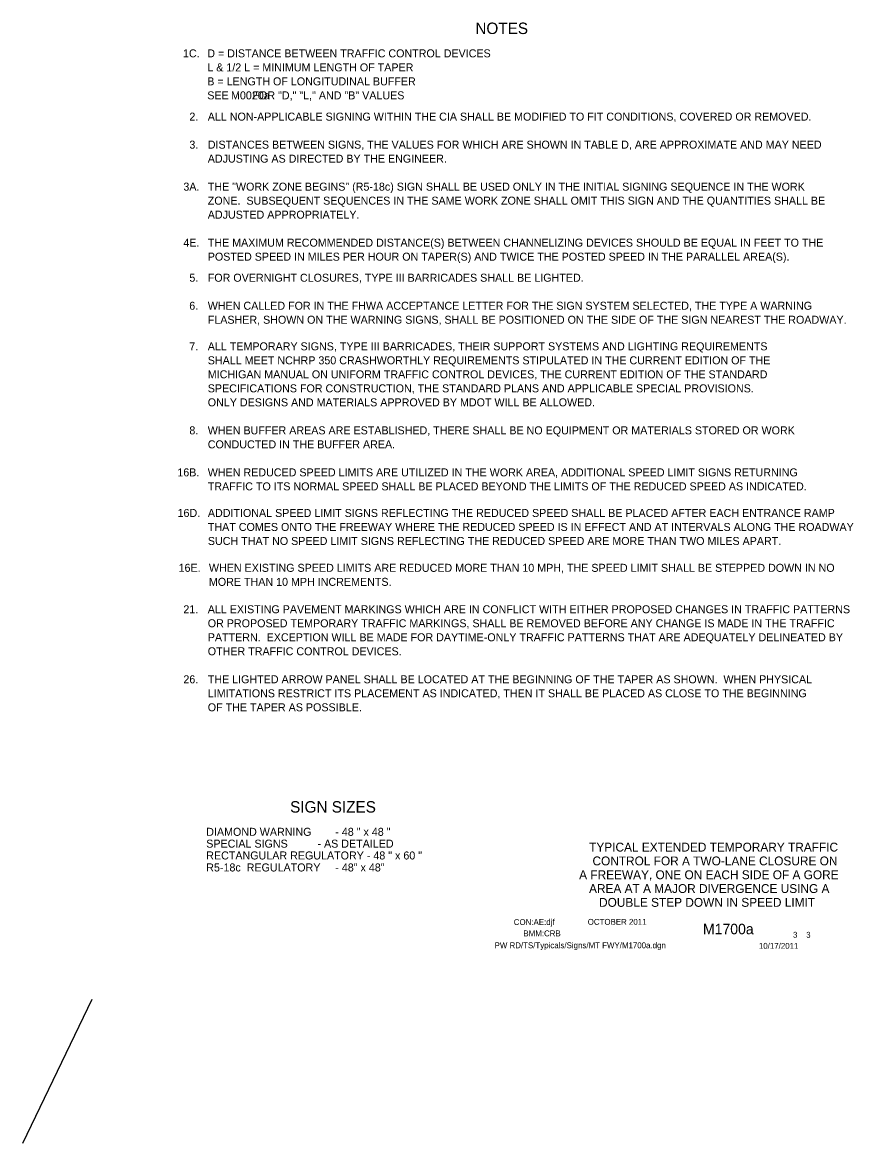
# Model space of a CAD drawing. Extents: x 16486 to 19505, y 5576 to 6998.
# Drawn here: x 18633 to 19505, y 5729 to 6905 of the extents above; entities that cross this region are included whole.
import ezdxf

# ---------------------------------------------------------------- set-up
doc = ezdxf.new("R2010")
doc.units = 0
for name, color, linetype in [('BORDER', 7, 'Continuous'), ('BORDER_SIGNAL_WO', 7, 'Continuous'), ('TYPICAL_TEXT_DIMEN_PR', 7, 'Continuous')]:
    doc.layers.add(name, color=color, linetype=linetype)

msp = doc.modelspace()

# ---------------------------------------------------------------- linework, layer by layer
at = {"layer": 'TYPICAL_TEXT_DIMEN_PR'}
msp.add_line((18705.8, 5880), (18633.1, 5728.7), dxfattribs=at)

# ---------------------------------------------------------------- texts
at = {"layer": 'BORDER'}
for s, p in [('TYPICAL EXTENDED TEMPORARY TRAFFIC', (19227.8, 6035.2)), ('CONTROL FOR A TWO-LANE CLOSURE ON', (19231.3, 6020.7)), ('A FREEWAY, ONE ON EACH SIDE OF A GORE', (19217.3, 6006.2)), ('AREA AT A MAJOR DIVERGENCE USING A', (19227.7, 5991.7)), ('DOUBLE STEP DOWN IN SPEED LIMIT', (19238.2, 5977.2))]:
    msp.add_text(s, height=9.3, dxfattribs=at).set_placement(p)
at = {"layer": 'BORDER_SIGNAL_WO'}
for s, height, p in [('CON:AE:djf  ', 6.2, (19148.7, 5958.1)), ('    OCTOBER 2011', 6.2, (19217.1, 5958.3)), ('    M1700a   ', 11, (19330.9, 5948.4)), ('BMM:CRB', 6.2, (19158.8, 5946.2)), (' 3    3 ', 6.2, (19439.4, 5944.7)), ('PW RD/TS/Typicals/Signs/MT FWY/M1700a.dgn      ', 6.2, (19128.6, 5933.7)), ('10/17/2011', 6.2, (19405.9, 5933.1))]:
    msp.add_text(s, height=height, dxfattribs=at).set_placement(p)
at = {"layer": 'TYPICAL_TEXT_DIMEN_PR'}
for s, height, p in [('NOTES', 12, (19108.4, 6893.3)), ('1C.', 8.4, (18801.6, 6868.8)), ('D = DISTANCE BETWEEN TRAFFIC CONTROL DEVICES', 8.4, (18827.1, 6868.8)), ('L & 1/2 L = MINIMUM LENGTH OF TAPER', 8.4, (18827.1, 6854.1)), ('B = LENGTH OF LONGITUDINAL BUFFER', 8.4, (18827.1, 6839.4)), ('SEE        FOR "D," "L," AND "B" VALUES', 8.4, (18827.1, 6824.7)), ('M0020a', 8.4, (18852, 6824.7)), ('2.', 8.4, (18808.3, 6802.4)), ('ALL NON-APPLICABLE SIGNING WITHIN THE CIA SHALL BE MODIFIED TO FIT CONDITIONS, COVERED OR REMOVED.', 8.4, (18827.6, 6802.4)), ('3.', 8.4, (18808.3, 6773)), ('DISTANCES BETWEEN SIGNS, THE VALUES FOR WHICH ARE SHOWN IN TABLE D, ARE APPROXIMATE AND MAY NEED', 8.4, (18827.6, 6773)), ('ADJUSTING AS DIRECTED BY THE ENGINEER.', 8.4, (18827.6, 6758.3)), ('3A.', 8.4, (18802, 6728.9)), ('THE "WORK ZONE BEGINS" (R5-18c) SIGN SHALL BE USED ONLY IN THE INITIAL SIGNING SEQUENCE IN THE WORK', 8.4, (18827.6, 6728.9)), ('ZONE.  SUBSEQUENT SEQUENCES IN THE SAME WORK ZONE SHALL OMIT THIS SIGN AND THE QUANTITIES SHALL BE', 8.4, (18827.6, 6714.2)), ('ADJUSTED APPROPRIATELY.', 8.4, (18827.6, 6699.5)), ('4E.', 8.4, (18802, 6670.1)), ('THE MAXIMUM RECOMMENDED DISTANCE(S) BETWEEN CHANNELIZING DEVICES SHOULD BE EQUAL IN FEET TO THE', 8.4, (18827.6, 6670.1)), ('POSTED SPEED IN MILES PER HOUR ON TAPER(S) AND TWICE THE POSTED SPEED IN THE PARALLEL AREA(S).', 8.4, (18827.6, 6655.4)), ('5.', 8.4, (18808.3, 6633.3)), ('FOR OVERNIGHT CLOSURES, TYPE III BARRICADES SHALL BE LIGHTED.', 8.4, (18827.6, 6633.3)), ('6.', 8.4, (18808.2, 6603.9)), ('WHEN CALLED FOR IN THE FHWA ACCEPTANCE LETTER FOR THE SIGN SYSTEM SELECTED, THE TYPE A WARNING ', 8.4, (18827.6, 6603.9)), ('FLASHER, SHOWN ON THE WARNING SIGNS, SHALL BE POSITIONED ON THE SIDE OF THE SIGN NEAREST THE ROADWAY.', 8.4, (18827.6, 6589.2)), ('7.', 8.4, (18808.2, 6561.3)), ('ALL TEMPORARY SIGNS, TYPE III BARRICADES, THEIR SUPPORT SYSTEMS AND LIGHTING REQUIREMENTS', 8.4, (18827.6, 6561.3)), ('SHALL MEET NCHRP 350 CRASHWORTHLY REQUIREMENTS STIPULATED IN THE CURRENT EDITION OF THE', 8.4, (18827.6, 6546.6)), ('MICHIGAN MANUAL ON UNIFORM TRAFFIC CONTROL DEVICES, THE CURRENT EDITION OF THE STANDARD', 8.4, (18827.6, 6531.9)), ('SPECIFICATIONS FOR CONSTRUCTION, THE STANDARD PLANS AND APPLICABLE SPECIAL PROVISIONS.', 8.4, (18827.6, 6517.2)), ('ONLY DESIGNS AND MATERIALS APPROVED BY MDOT WILL BE ALLOWED.', 8.4, (18827.6, 6502.5)), ('8.', 8.4, (18808.3, 6473.1)), ('WHEN BUFFER AREAS ARE ESTABLISHED, THERE SHALL BE NO EQUIPMENT OR MATERIALS STORED OR WORK     ', 8.4, (18827.6, 6473.1)), ('CONDUCTED IN THE BUFFER AREA.', 8.4, (18827.6, 6458.4)), ('16B.', 8.4, (18795.7, 6429)), ('WHEN REDUCED SPEED LIMITS ARE UTILIZED IN THE WORK AREA, ADDITIONAL SPEED LIMIT SIGNS RETURNING', 8.4, (18827.6, 6429)), ('TRAFFIC TO ITS NORMAL SPEED SHALL BE PLACED BEYOND THE LIMITS OF THE REDUCED SPEED AS INDICATED.', 8.4, (18827.6, 6414.3)), ('16D.', 8.4, (18795.9, 6386.4)), ('ADDITIONAL SPEED LIMIT SIGNS REFLECTING THE REDUCED SPEED SHALL BE PLACED AFTER EACH ENTRANCE RAMP', 8.4, (18827.7, 6386.4)), ('THAT COMES ONTO THE FREEWAY WHERE THE REDUCED SPEED IS IN EFFECT AND AT INTERVALS ALONG THE ROADWAY', 8.4, (18827.7, 6371.7)), ('SUCH THAT NO SPEED LIMIT SIGNS REFLECTING THE REDUCED SPEED ARE MORE THAN TWO MILES APART.', 8.4, (18827.7, 6357)), ('16E.', 8.4, (18797, 6328.8)), ('WHEN EXISTING SPEED LIMITS ARE REDUCED MORE THAN 10 MPH, THE SPEED LIMIT SHALL BE STEPPED DOWN IN NO', 8.4, (18828.8, 6328.8)), ('MORE THAN 10 MPH INCREMENTS.', 8.4, (18828.8, 6314.1)), ('21.', 8.4, (18802, 6285.3)), ('ALL EXISTING PAVEMENT MARKINGS WHICH ARE IN CONFLICT WITH EITHER PROPOSED CHANGES IN TRAFFIC PATTERNS', 8.4, (18827.6, 6285.3)), ('OR PROPOSED TEMPORARY TRAFFIC MARKINGS, SHALL BE REMOVED BEFORE ANY CHANGE IS MADE IN THE TRAFFIC', 8.4, (18827.6, 6270.6)), ('PATTERN.  EXCEPTION WILL BE MADE FOR DAYTIME-ONLY TRAFFIC PATTERNS THAT ARE ADEQUATELY DELINEATED BY', 8.4, (18827.6, 6255.9)), ('OTHER TRAFFIC CONTROL DEVICES.', 8.4, (18827.6, 6241.2)), ('26.', 8.4, (18802, 6211.8)), ('THE LIGHTED ARROW PANEL SHALL BE LOCATED AT THE BEGINNING OF THE TAPER AS SHOWN.  WHEN PHYSICAL', 8.4, (18827.6, 6211.8)), ('LIMITATIONS RESTRICT ITS PLACEMENT AS INDICATED, THEN IT SHALL BE PLACED AS CLOSE TO THE BEGINNING', 8.4, (18827.6, 6197.1)), ('OF THE TAPER AS POSSIBLE.', 8.4, (18827.6, 6182.4)), ('SIGN SIZES', 12, (18914, 6076.1)), ('DIAMOND WARNING        - 48 " x 48 "', 8.4, (18826, 6051.7)), ('SPECIAL SIGNS          - AS DETAILED', 8.4, (18826, 6039.3)), ('RECTANGULAR REGULATORY - 48 " x 60 "', 8.4, (18826, 6026.9)), ('R5-18c  REGULATORY     - 48" x 48"', 8.4, (18826, 6014.3))]:
    msp.add_text(s, height=height, dxfattribs=at).set_placement(p)

doc.saveas('drawing.dxf')
